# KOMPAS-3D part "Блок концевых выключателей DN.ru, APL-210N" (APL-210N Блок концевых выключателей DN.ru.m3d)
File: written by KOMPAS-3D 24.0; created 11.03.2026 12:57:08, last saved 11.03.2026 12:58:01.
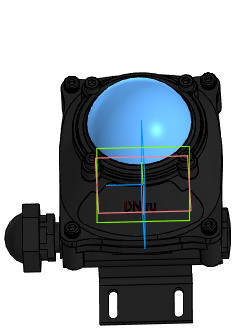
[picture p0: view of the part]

Document properties: Автор: R2D2; Полное имя файла: E:\Работа\Зайцев\БКВ APL-210N Блок концевых выключателей DN.ru\APL-210N Блок концевых выключателей DN.ru.m3d

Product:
- Part/product: Блок концевых выключателей DN.ru  | designation APL-210N
    Масса: 0.22
    Раздел спецификации: Прочие изделия
    Примечание: D290-00322

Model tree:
1. Операция без истории:1

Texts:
  APL-210N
